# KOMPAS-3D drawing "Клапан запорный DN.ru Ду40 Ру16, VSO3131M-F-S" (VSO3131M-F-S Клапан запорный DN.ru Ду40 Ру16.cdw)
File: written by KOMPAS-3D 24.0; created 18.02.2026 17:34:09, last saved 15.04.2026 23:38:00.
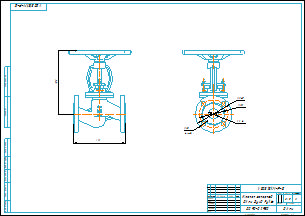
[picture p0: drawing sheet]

Document properties: Автор: R2D2; Форматы листов документа: A2; Полное имя файла: VSO3131M-F-S Клапан запорный DN.ru Ду40 Ру16.m3d; Масса: 8.25; Наименование: Клапан запорный DN.ru Ду40 Ру16; Количество листов документа: 1; Примечание: D090-02950

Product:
- Component [detail]: Корпус  | qty 1  | pos. 1  | Масса: 6.9; Автор: R2D2; source file: исходные материалы\Корпус.m3d
- Component [detail]: Клапан запорный DN.ru Ду40 Ру16  | designation VSO1121M-F-S  | qty 1  | pos. 2  | Масса: 9.32; Раздел спецификации: Прочие изделия; Примечание: D090-01946; Автор: R2D2; source file: исходные материалы\2.m3d
- Component [standard]: Hexagon head screw ISO 4017 - М10 x 20  | qty 4  | Масса: 0.023019; Раздел спецификации: Стандартные изделия; Рассекать на разрезах: no
- Part/product: Клапан запорный DN.ru Ду40 Ру16  | designation VSO3131M-F-S
    Масса: 8.25
    Раздел спецификации: Прочие изделия
    Примечание: D090-02950

Views: Вид 1, Спереди
Referenced files in E:\Работа\Зайцев\VSO3131M-F-S Клапан запорный DN.ru Ду15-100 Ру40\DN40\: VSO3131M-F-S Клапан запорный DN.ru Ду40 Ру40.m3d
Referenced files in E:\Работа\Зайцев\VSO3131M-F-S Клапан запорный DN.ru Ду15-100 Ру16\DN40\: VSO3131M-F-S Клапан запорный DN.ru Ду40 Ру16.m3d
Referenced files in E:\Работа\Зайцев\Для компаса\: чертеж DN.ru А3.cdt
Referenced files in E:\Работа\Зайцев\VSO3131M-F-S Клапан запорный DN.ru Ду15-100 Ру16\DN40\исходные материалы\: Корпус.m3d, 2.m3d
Referenced files in C:\Program Files\ASCON\KOMPAS-3D v24\Libs\PolynomLib\DATA\vault\Methods\Kompas\3D\: PLib_Bolt_1_ISO_1100.m3d
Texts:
  VSO3131M-F-S
  чертеж DN.ru А3.cdt
  Клапан запорный
  DN.ru Ду40 Ру16
  Труба
  Колонна
  Ребро жесткости
  ОТЛИВКА
  ЛЕЙБЛ
  Фланец верх
  Фланец
  отвертие во фланце
  Труба / Нестандартная труба / L = 100.7 мм
  Труба Нестандартная труба L = 100.7 мм
  Корпус
  Клапан запорный DN.ru Ду40 Ру16
  VSO1121M-F-S
  VSO1121M-F-S Клапан запорный DN.ru Ду40 Ру16
  Hexagon head screw ISO 4017 - М10 x 20
  VSO3131M-F-S Клапан запорный DN.ru Ду40 Ру16
Dimensions and other numbers on the sheet: 0; 3; 2; 4; 200; 250; 1:2; 1; 8,25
